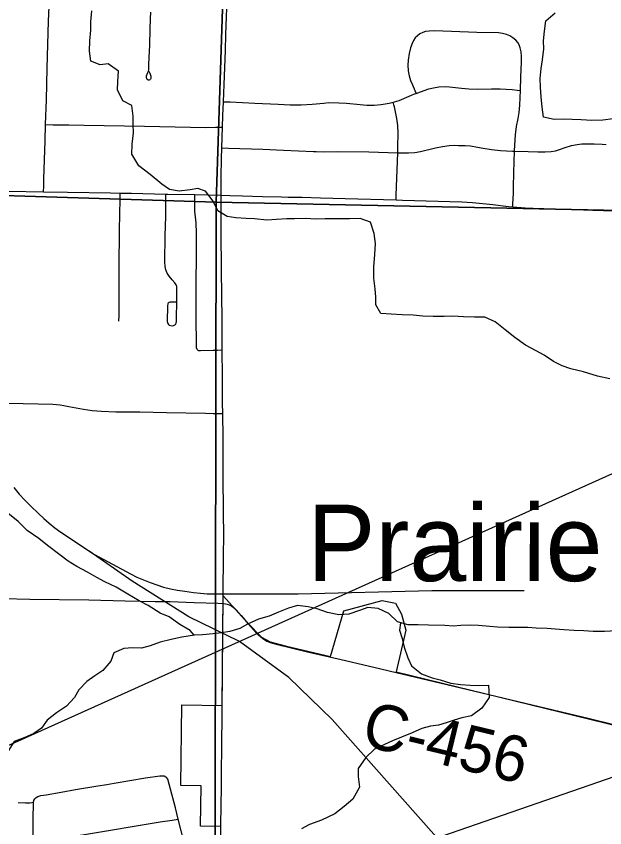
# Model space of a CAD drawing. Extents: x 0 to 34, y 0 to 22.
# Drawn here: x 7.454 to 8.183, y 16.761 to 17.768 of the extents above; entities that cross this region are included whole.
import ezdxf

# ---------------------------------------------------------------- set-up
doc = ezdxf.new("R2010")
doc.units = 0
for name, color, linetype in [('GM_X_City_Street', 7, 'Continuous'), ('GM_X_Corporation', 7, 'Continuous'), ('GM_X_County_Road', 7, 'Continuous'), ('GM_X_County_Road_Text', 7, 'Continuous'), ('GM_X_Minor_River', 7, 'Continuous'), ('GM_X_Minor_River_Text', 7, 'Continuous'), ('GM_X_Rail_Line', 7, 'Continuous'), ('SH_Data', 7, 'Continuous')]:
    doc.layers.add(name, color=color, linetype=linetype)

msp = doc.modelspace()

# ---------------------------------------------------------------- linework, layer by layer
at = {"layer": 'GM_X_City_Street'}
for points in [[(7.4876, 17.5503), (7.4877, 17.5578), (7.4878, 17.5627), (7.488, 17.5664), (7.4895, 17.6136), (7.4901, 17.6339), (7.491, 17.6645), (7.4922, 17.7037), (7.4929, 17.7332), (7.4938, 17.762), (7.4944, 17.7799), (7.4947, 17.7908), (7.4948, 17.8048)], [(7.618, 17.6999), (7.6192, 17.6976), (7.6198, 17.6961), (7.6205, 17.6938), (7.6206, 17.6928), (7.6206, 17.6919), (7.6204, 17.6909), (7.6201, 17.6902), (7.6194, 17.6893), (7.6183, 17.6889), (7.6171, 17.689), (7.6161, 17.6897), (7.6154, 17.6907), (7.615, 17.6925), (7.6153, 17.6943), (7.6168, 17.6982), (7.6174, 17.6994), (7.6178, 17.7002), (7.618, 17.7018), (7.6181, 17.7036), (7.6182, 17.7086), (7.6189, 17.7247), (7.6193, 17.7319), (7.6194, 17.7387), (7.6197, 17.746), (7.6198, 17.7506), (7.6199, 17.7557), (7.62, 17.7611), (7.6201, 17.7653), (7.6204, 17.7734)], [(8.0691, 17.5318), (8.0693, 17.5349), (8.07, 17.5486), (8.0702, 17.5559), (8.0705, 17.5741), (8.0713, 17.6007), (8.0713, 17.6014), (8.0724, 17.6211), (8.0738, 17.6315), (8.0758, 17.6413), (8.077, 17.6487), (8.078, 17.658), (8.0786, 17.6759), (8.0792, 17.6928), (8.0802, 17.7109), (8.0801, 17.7184), (8.0795, 17.7241), (8.0783, 17.729), (8.077, 17.7326), (8.0753, 17.7354), (8.0728, 17.7384), (8.0694, 17.7413), (8.0656, 17.7437), (8.0615, 17.7455), (8.0565, 17.7468), (8.0515, 17.7474), (8.0248, 17.7482), (7.972, 17.7499), (7.9657, 17.7498), (7.9612, 17.7492), (7.9575, 17.748), (7.954, 17.7463), (7.9509, 17.744), (7.9482, 17.7412), (7.946, 17.738), (7.9444, 17.7345), (7.9426, 17.7291), (7.9409, 17.7218), (7.9397, 17.7137), (7.9393, 17.7074), (7.9397, 17.7005), (7.9408, 17.6943), (7.9426, 17.6884), (7.9448, 17.6831), (7.9478, 17.6762), (7.9495, 17.6725)], [(7.7105, 17.6621), (7.7188, 17.6618), (7.7493, 17.6605), (7.7785, 17.6589), (7.7933, 17.6581), (7.8069, 17.6581), (7.8205, 17.6591), (7.8351, 17.6605), (7.841, 17.661), (7.8535, 17.6609), (7.8629, 17.6605), (7.8802, 17.6585), (7.8882, 17.6579), (7.8974, 17.6579), (7.906, 17.6585), (7.9158, 17.6602), (7.921, 17.6614), (7.9224, 17.6618), (7.9282, 17.6637), (7.9436, 17.6702), (7.9474, 17.6717), (7.9495, 17.6725), (7.9547, 17.6744), (7.9653, 17.678), (7.9708, 17.6794), (7.9777, 17.6804), (7.9864, 17.6809), (7.9909, 17.6806), (8.0057, 17.6788), (8.0149, 17.6781), (8.0254, 17.6778), (8.0428, 17.6782), (8.0534, 17.6782), (8.0686, 17.6771), (8.0747, 17.6764), (8.0786, 17.6759)], [(7.9245, 17.5403), (7.9247, 17.546), (7.9266, 17.5985), (7.9269, 17.6064), (7.9271, 17.6232), (7.9265, 17.6326), (7.9253, 17.6412), (7.9225, 17.6559), (7.9218, 17.6583), (7.921, 17.6614)], [(7.4901, 17.6339), (7.4994, 17.6336), (7.5019, 17.6335), (7.5187, 17.6333), (7.538, 17.6329), (7.6127, 17.6317), (7.6886, 17.6302), (7.7005, 17.6304), (7.7094, 17.6305)], [(7.7086, 17.6049), (7.7166, 17.6046), (7.7595, 17.6034), (7.7849, 17.6021), (7.8222, 17.6003), (7.8253, 17.6002), (7.834, 17.6001), (7.8514, 17.6002), (7.8906, 17.5998), (7.9266, 17.5985), (7.9273, 17.5985), (7.9398, 17.5986), (7.9479, 17.5991), (7.9547, 17.6002), (7.9735, 17.6048), (7.9819, 17.6065), (7.9905, 17.6076), (7.9966, 17.6081), (8.0018, 17.608), (8.0058, 17.608), (8.01, 17.6078), (8.0167, 17.6073), (8.0256, 17.6058), (8.0323, 17.6045), (8.0428, 17.6027), (8.054, 17.6015), (8.0689, 17.6008), (8.0713, 17.6007), (8.0883, 17.6002), (8.1004, 17.5998), (8.1093, 17.5998), (8.1169, 17.6003), (8.1222, 17.6012), (8.1273, 17.6027), (8.1343, 17.6054), (8.142, 17.6078), (8.1492, 17.6092), (8.1546, 17.6097), (8.1701, 17.6097), (8.18, 17.6093), (8.1848, 17.609)], [(7.581, 17.3899), (7.5811, 17.3968), (7.5811, 17.4298), (7.5814, 17.4484), (7.5813, 17.464), (7.5814, 17.4727), (7.5816, 17.487), (7.5818, 17.5037), (7.5821, 17.5218), (7.5824, 17.5415), (7.5826, 17.5488)], [(7.6524, 17.4133), (7.6443, 17.4134), (7.6431, 17.4131), (7.6422, 17.4123), (7.6416, 17.4112), (7.6412, 17.4088), (7.6409, 17.3895), (7.6414, 17.3871), (7.6424, 17.3855), (7.6433, 17.3848), (7.6451, 17.3843), (7.6476, 17.3842), (7.6494, 17.3847), (7.651, 17.3856), (7.652, 17.3872), (7.6525, 17.3896), (7.6528, 17.4182), (7.6529, 17.4269), (7.6529, 17.4304), (7.6526, 17.433), (7.6518, 17.435), (7.6503, 17.4373), (7.6471, 17.441), (7.6432, 17.4458), (7.6409, 17.4495), (7.6393, 17.4536), (7.6384, 17.4578), (7.638, 17.4634), (7.6381, 17.4957), (7.639, 17.5199), (7.6392, 17.533), (7.6392, 17.5417), (7.6391, 17.5476)], [(7.709, 17.3539), (7.7031, 17.3536), (7.6975, 17.3534), (7.6819, 17.3529), (7.6801, 17.3531), (7.6791, 17.3536), (7.6778, 17.3546), (7.6772, 17.3568), (7.6771, 17.3607), (7.6768, 17.3945), (7.6768, 17.4219), (7.6771, 17.4864), (7.6773, 17.4992), (7.6769, 17.512), (7.6751, 17.5262), (7.6749, 17.5349), (7.675, 17.5411), (7.6751, 17.5468)], [(7.4562, 16.7925), (7.4651, 16.7924), (7.4704, 16.7924), (7.473, 16.7925), (7.4749, 16.7932), (7.4757, 16.7949), (7.4768, 16.797), (7.4782, 16.7989), (7.4805, 16.8), (7.4841, 16.8014), (7.4906, 16.8023), (7.5094, 16.8054), (7.5272, 16.8087), (7.5548, 16.8132), (7.5659, 16.8151), (7.5751, 16.8165), (7.6138, 16.8231), (7.6317, 16.8257), (7.6343, 16.8258), (7.637, 16.8255), (7.639, 16.8245)], [(7.6688, 16.7193), (7.6668, 16.7249), (7.6656, 16.7284), (7.6617, 16.743), (7.6546, 16.7718), (7.6511, 16.786), (7.6432, 16.8155), (7.6415, 16.8215), (7.6403, 16.8234), (7.639, 16.8245)], [(7.48, 16.6728), (7.4781, 16.6737), (7.4765, 16.6751), (7.4753, 16.6768), (7.4743, 16.6793), (7.4741, 16.6823), (7.4742, 16.6892), (7.4743, 16.7105), (7.4746, 16.7424), (7.4748, 16.774), (7.475, 16.7901), (7.4749, 16.7932)], [(7.4746, 16.7424), (7.4812, 16.7435), (7.507, 16.7478), (7.5383, 16.7529), (7.632, 16.7685), (7.6468, 16.7706), (7.6546, 16.7718)]]:
    msp.add_lwpolyline(points, dxfattribs=at)
at = {"layer": 'GM_X_Corporation'}
for points in [[(6.72, 18.5734), (7.7346, 18.5471), (7.7016, 17.5373), (6.7004, 17.5689)], [(7.7346, 18.5471), (8.7846, 18.5318), (8.7625, 17.5156), (7.7016, 17.5373)], [(6.7004, 17.5689), (7.7016, 17.5373), (7.6999, 16.5369), (6.6829, 16.5538)], [(7.7016, 17.5373), (8.7625, 17.5156), (8.7104, 16.5149), (7.6999, 16.5369)]]:
    msp.add_lwpolyline(points, close=True, dxfattribs=at)
msp.add_lwpolyline([(7.7067, 16.7147), (7.7074, 16.7628), (7.6823, 16.7633), (7.6828, 16.8133), (7.6578, 16.8139), (7.659, 16.914), (7.709, 16.9128), (7.7104, 17.049), (7.7218, 17.0363), (7.7407, 17.0151), (7.7579, 16.9977), (7.7684, 16.9919), (7.7885, 16.9866), (7.8434, 16.9737), (7.8597, 17.0305), (7.9072, 17.0431), (7.9239, 17.0398), (7.9312, 17.0262), (7.9366, 17.0065), (7.9245, 16.9546), (8.4774, 16.8197)], dxfattribs=at)
at = {"layer": 'GM_X_County_Road'}
for p, q in [((7.7086, 17.6049), (7.7094, 17.6305)), ((7.7102, 17.0395), (7.7102, 17.0475)), ((7.7089, 16.9013), (7.7089, 16.911))]:
    msp.add_line(p, q, dxfattribs=at)
for points in [[(7.7105, 17.6621), (7.7113, 17.6836), (7.7129, 17.7258), (7.7135, 17.7457), (7.7156, 17.8007)], [(7.7094, 17.6305), (7.7099, 17.6451), (7.7105, 17.6621)], [(7.7077, 17.5461), (7.7076, 17.5547), (7.7077, 17.569), (7.7081, 17.5911), (7.7086, 17.6049)], [(7.3903, 17.5522), (7.401, 17.5519), (7.4439, 17.5511), (7.4876, 17.5503)], [(7.4876, 17.5503), (7.5172, 17.5498), (7.5706, 17.549), (7.5826, 17.5488)], [(7.5826, 17.5488), (7.5967, 17.5485), (7.6391, 17.5476)], [(7.6391, 17.5476), (7.6415, 17.5476), (7.6751, 17.5468)], [(7.6751, 17.5468), (7.6912, 17.5465), (7.7077, 17.5461)], [(7.7077, 17.5461), (7.7186, 17.5456), (7.7343, 17.5452), (7.7591, 17.5445), (7.7826, 17.544), (7.7906, 17.5438), (7.808, 17.5435), (7.831, 17.5428), (7.8614, 17.542), (7.9245, 17.5403)], [(7.709, 17.3539), (7.7089, 17.3629), (7.7088, 17.3971), (7.7085, 17.4169), (7.7085, 17.4256), (7.7082, 17.4499), (7.7081, 17.4611), (7.7079, 17.4928), (7.7079, 17.5175), (7.7077, 17.5345), (7.7077, 17.5461)], [(7.9245, 17.5403), (7.9323, 17.54), (8.0061, 17.5378), (8.0191, 17.5369), (8.0446, 17.5345), (8.0637, 17.5323), (8.0691, 17.5318)], [(8.0691, 17.5318), (8.0847, 17.5305), (8.0946, 17.53), (8.1212, 17.5291), (8.1685, 17.5274), (8.2082, 17.5264), (8.248, 17.5254), (8.3108, 17.5243)], [(7.7096, 17.2752), (7.7095, 17.2883), (7.7094, 17.3131), (7.7094, 17.3218), (7.709, 17.3539)], [(7.3979, 17.2892), (7.4087, 17.2889), (7.4442, 17.2879), (7.4989, 17.2867), (7.5083, 17.2859), (7.5125, 17.2852)], [(7.5125, 17.2852), (7.5187, 17.284), (7.537, 17.2805), (7.548, 17.279), (7.5592, 17.2781), (7.5771, 17.2775), (7.607, 17.2774), (7.6399, 17.2765), (7.6884, 17.2756), (7.6978, 17.2754), (7.7096, 17.2752)], [(7.7102, 17.0475), (7.7104, 17.0596), (7.7104, 17.0696), (7.7105, 17.0817), (7.7108, 17.1007), (7.7109, 17.1223), (7.7106, 17.154), (7.7105, 17.1689), (7.7104, 17.1819), (7.7102, 17.2037), (7.7102, 17.2248), (7.71, 17.246), (7.7096, 17.2746), (7.7096, 17.2752)], [(7.3136, 17.0477), (7.3289, 17.0473), (7.3568, 17.0468), (7.4019, 17.0466), (7.4377, 17.0459), (7.4704, 17.0451), (7.5435, 17.0439), (7.5886, 17.0429), (7.6259, 17.0422), (7.6446, 17.042), (7.6741, 17.0409), (7.7035, 17.0398), (7.7102, 17.0395)], [(7.7098, 16.9993), (7.7099, 17.0102), (7.7102, 17.0395)], [(7.7102, 17.0395), (7.713, 17.039), (7.7151, 17.0385), (7.7176, 17.0378), (7.7193, 17.037), (7.7211, 17.0361), (7.7227, 17.035), (7.7246, 17.0333), (7.7264, 17.0316), (7.7325, 17.0248), (7.741, 17.0145)], [(7.741, 17.0145), (7.7511, 17.0033), (7.7568, 16.9981), (7.7604, 16.9954), (7.7643, 16.993), (7.7685, 16.9912), (7.7743, 16.9893), (7.8165, 16.9792), (7.8421, 16.9733)], [(7.7089, 16.911), (7.7089, 16.912), (7.7089, 16.9185), (7.7092, 16.9437), (7.7093, 16.9599), (7.7095, 16.9692), (7.7097, 16.9885), (7.7098, 16.9993)], [(7.8421, 16.9733), (7.8618, 16.9687), (7.9056, 16.9583), (7.9246, 16.9539)], [(7.9246, 16.9539), (7.9874, 16.9389), (8.0221, 16.9307), (8.1644, 16.8968), (8.2248, 16.882)], [(7.7075, 16.7611), (7.7075, 16.7621), (7.7078, 16.7914), (7.708, 16.8091), (7.7082, 16.8225), (7.7087, 16.8696), (7.7089, 16.8954), (7.7089, 16.9013)]]:
    msp.add_lwpolyline(points, dxfattribs=at)
at = {"layer": 'GM_X_Minor_River'}
for points in [[(8.1895, 17.3182), (8.1744, 17.3215), (8.157, 17.3268), (8.1412, 17.3309), (8.1303, 17.3345), (8.1197, 17.3396), (8.1081, 17.3478), (8.098, 17.353), (8.0849, 17.36), (8.0718, 17.3694), (8.0598, 17.3791), (8.0475, 17.3892), (8.0347, 17.3948), (8.0218, 17.3947), (8.0082, 17.3953), (7.9949, 17.3959), (7.9843, 17.3958), (7.9706, 17.3956), (7.9578, 17.3959), (7.9456, 17.3973), (7.932, 17.3975), (7.9184, 17.3986), (7.9055, 17.3992), (7.8996, 17.4099), (7.8994, 17.4198), (7.8985, 17.4301), (7.8969, 17.443), (7.8968, 17.4574), (7.8982, 17.4726), (7.8992, 17.4862), (7.8975, 17.4988), (7.8929, 17.5125), (7.8801, 17.5173), (7.8668, 17.5168), (7.8509, 17.5168), (7.8365, 17.517), (7.8251, 17.5165), (7.8118, 17.5171), (7.7985, 17.517), (7.7891, 17.5168), (7.7762, 17.5159), (7.7644, 17.515), (7.7492, 17.5168), (7.7386, 17.5174), (7.7258, 17.518), (7.7152, 17.5198), (7.7036, 17.5268), (7.6977, 17.5387), (7.6885, 17.551), (7.6787, 17.5543), (7.6692, 17.5529), (7.6555, 17.5513), (7.6438, 17.553), (7.634, 17.5597), (7.6195, 17.5717), (7.6057, 17.5826), (7.5968, 17.5972), (7.5975, 17.6093), (7.5989, 17.6237), (7.5987, 17.6344), (7.5985, 17.6442), (7.5969, 17.6575), (7.586, 17.6634), (7.5794, 17.6769), (7.5796, 17.6871), (7.5806, 17.7), (7.5675, 17.709), (7.5576, 17.708), (7.546, 17.7124), (7.5447, 17.725), (7.5449, 17.7375), (7.5463, 17.7507), (7.5462, 17.7614), (7.5472, 17.775)], [(8.1938, 17.6407), (8.1809, 17.6394), (8.1672, 17.6389), (8.154, 17.6395), (8.1426, 17.6401), (8.1331, 17.6403), (8.1206, 17.6402), (8.1074, 17.6431), (8.1057, 17.6553), (8.1045, 17.6682), (8.1035, 17.68), (8.103, 17.691), (8.1044, 17.7035), (8.1061, 17.7141), (8.1075, 17.7277), (8.1073, 17.7376), (8.1087, 17.7497), (8.1101, 17.7626), (8.1216, 17.7726)], [(7.6743, 17.0002), (7.6692, 17.0061), (7.6565, 17.0135), (7.6434, 17.0229), (7.6321, 17.0277), (7.6171, 17.0371), (7.6059, 17.043), (7.592, 17.0512), (7.5777, 17.0598), (7.5635, 17.0666), (7.5537, 17.0717), (7.5421, 17.0784), (7.5286, 17.0855), (7.5181, 17.0921), (7.5076, 17.0999), (7.4923, 17.1116), (7.4818, 17.1201), (7.4672, 17.1303), (7.4561, 17.1411), (7.4434, 17.1516)], [(8.1978, 17.0057), (8.183, 17.0048), (8.169, 17.0047), (8.1573, 17.0057), (8.1451, 17.0059), (8.1323, 17.007), (8.1217, 17.0075), (8.1118, 17.0085), (8.0982, 17.0088), (8.0879, 17.0097), (8.0758, 17.0099), (8.0644, 17.0098), (8.0504, 17.0101), (8.0406, 17.011), (8.0266, 17.0124), (8.0167, 17.0126), (8.0049, 17.0121), (7.9951, 17.0115), (7.9849, 17.0121), (7.9648, 17.0125), (7.9519, 17.0131), (7.9394, 17.013), (7.9262, 17.0166), (7.9154, 17.0271), (7.9022, 17.0334), (7.8897, 17.0344), (7.879, 17.0308), (7.866, 17.0262), (7.8535, 17.0253), (7.8395, 17.0282), (7.8267, 17.033), (7.8154, 17.0355), (7.8022, 17.0369), (7.7911, 17.0337), (7.7789, 17.0286), (7.7674, 17.0239), (7.7541, 17.02), (7.7403, 17.0138), (7.7307, 17.0087), (7.7185, 17.0047), (7.7082, 17.003), (7.698, 17.0021), (7.6847, 17.0008), (7.6748, 17.0003), (7.6588, 16.9976), (7.6459, 16.9948), (7.6322, 16.9916), (7.6196, 16.9869), (7.6089, 16.9841), (7.5979, 16.9847), (7.5869, 16.9838), (7.5746, 16.9783), (7.571, 16.9678), (7.5609, 16.9562), (7.551, 16.9499), (7.5414, 16.9429), (7.5313, 16.9325)], [(7.9299, 17.0156), (7.9286, 17.0064), (7.9322, 16.996), (7.9347, 16.9854), (7.9393, 16.972), (7.9437, 16.962), (7.956, 16.9523), (7.9692, 16.9475), (7.979, 16.945), (7.9922, 16.9406), (8.0043, 16.9392), (8.0164, 16.9382), (8.0263, 16.9377), (8.0392, 16.9382), (8.04, 16.923), (8.031, 16.9095), (8.018, 16.9003), (8.0061, 16.8975), (7.9966, 16.8946), (7.9867, 16.8914), (7.9772, 16.8885), (7.9673, 16.8872), (7.9566, 16.8844), (7.9444, 16.8789), (7.9314, 16.8735), (7.9203, 16.8691), (7.9103, 16.8644), (7.8977, 16.8586), (7.8869, 16.8485), (7.8775, 16.8347), (7.8777, 16.8248), (7.8793, 16.8115), (7.8711, 16.7969), (7.8603, 16.7876), (7.8488, 16.7787), (7.8319, 16.7707), (7.8174, 16.7653), (7.8071, 16.7598)], [(7.5313, 16.9325), (7.5258, 16.9227), (7.5161, 16.9123), (7.5034, 16.9038), (7.4919, 16.8949), (7.4852, 16.8848), (7.4756, 16.8782), (7.4642, 16.8731), (7.4512, 16.8684), (7.4433, 16.8557), (7.4404, 16.8428), (7.4387, 16.8318), (7.4396, 16.8197), (7.425, 16.8101), (7.4125, 16.8084), (7.3987, 16.8042), (7.3873, 16.7995), (7.3739, 16.7967), (7.3598, 16.7932), (7.3483, 16.7858), (7.3375, 16.7765), (7.3264, 16.771), (7.313, 16.7641), (7.3004, 16.7579)]]:
    msp.add_lwpolyline(points, dxfattribs=at)
at = {"layer": 'GM_X_Rail_Line'}
for points in [[(7.4509, 17.1833), (7.4575, 17.1753), (7.4644, 17.1676), (7.4716, 17.1602), (7.4811, 17.151), (7.4877, 17.1448), (7.4946, 17.139), (7.5017, 17.1335), (7.5091, 17.1282), (7.5507, 17.1002), (7.5953, 17.0764), (7.6032, 17.0723), (7.6113, 17.0687), (7.6195, 17.0654), (7.6279, 17.0625), (7.6364, 17.06), (7.645, 17.0578), (7.6537, 17.0561), (7.6625, 17.0547), (7.6735, 17.0532), (7.6819, 17.0523), (7.6904, 17.0517), (7.6989, 17.0516), (7.8032, 17.0516), (7.9689, 17.0555), (8.0833, 17.0555)], [(8.1578, 14.5086), (8.1698, 15.5158), (8.179, 16.303), (8.179, 16.3934), (8.1652, 16.4746), (8.1423, 16.5389), (8.1055, 16.594), (8.0627, 16.6538), (7.9876, 16.735), (7.8453, 16.8958), (7.7917, 16.9478), (7.7304, 16.9923), (7.6677, 17.0229), (7.5972, 17.0673), (7.5441, 17.1046)]]:
    msp.add_lwpolyline(points, dxfattribs=at)
at = {"layer": 'SH_Data'}
msp.add_lwpolyline([(4.574, 15.5703), (9.2813, 17.2011), (9.2813, 17.6911)], close=True, dxfattribs=at)

# ---------------------------------------------------------------- texts
at = {"layer": 'GM_X_County_Road_Text'}
msp.add_text('C-456', height=0.05682, rotation=346.4304, dxfattribs=at).set_placement((7.8795, 16.864))
at = {"layer": 'GM_X_Minor_River_Text'}
msp.add_text('Prairie', height=0.09476, rotation=359.9856, dxfattribs=at).set_placement((7.8143, 17.0674))

doc.saveas('drawing.dxf')
